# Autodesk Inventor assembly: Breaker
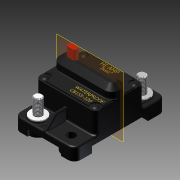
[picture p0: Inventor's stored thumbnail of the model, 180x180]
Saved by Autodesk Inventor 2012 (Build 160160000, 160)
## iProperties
Shininess: 64.0
Angle Display Precision: 2
Document Length Units: 11272
Document Angle Units: 11279
Document Time Units: 11290
Document Mass Units: 11286
Document Length Units Precision: 3
Document Angle Units Precision: 2
Compacted: False
Created: 2004-01
Part Number: Breaker
Document SubType Name: Assembly
Designer: t8558es
Density: 0.0
Volumn: 0.0
Area: 0.0
PropertySet Name: Model Information
Control State: 0
Master: False
Checked Out: False
Author: t8558es
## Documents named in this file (3)
- R:\CAD Archives\Electronics_1764\Breaker_1764\Breaker_1764\Breaker_1764.iam
- R:\CAD Archives\Electronics_1764\Breaker_1764\Breaker_1764\Breaker_Body_1764.ipt
- R:\CAD Archives\Electronics_1764\Breaker_1764\Breaker_1764\Breaker_Post_1764.ipt
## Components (3 placed, 2 different names)
1. Breaker_Body_1764:1 — Mate:1, Mate:2, Mate:3, Mate:4
2. Breaker_Post_1764:1 — Mate:1, Mate:2
3. Breaker_Post_1764:2 — Mate:3, Mate:4
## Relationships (4: Mate 4)
- Mate:1: Breaker_Body_1764:1 ↔ Breaker_Post_1764:1
- Mate:2: Breaker_Body_1764:1 ↔ Breaker_Post_1764:1
- Mate:3: Breaker_Body_1764:1 ↔ Breaker_Post_1764:2
- Mate:4: Breaker_Body_1764:1 ↔ Breaker_Post_1764:2
